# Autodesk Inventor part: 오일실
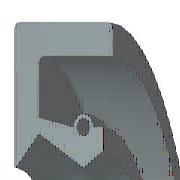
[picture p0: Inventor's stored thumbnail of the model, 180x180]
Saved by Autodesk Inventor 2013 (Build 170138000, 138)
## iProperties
Created: 2021-07
Part Number: 오일실
Material: 고무
Description: 오일-실
Document SubType Name: Modeling
Standard: KS B 2804
Designer: mdu
Standards Organization: KS
Language: ko-KR
Size Designation: D - 10 20 7
Categories: <MemberInstance><Categories><Category DisplayName="샤프트 부품" InternalName="7f7aeb1f-a693-4053-b835-cee3144e0d98" Mnemonic="SHFT"><Category DisplayName="실링" Intern
Density: 0.93 g/cm^3
Mass: 1.11329 g
Surface Area: 16.3871 cm^2
Volume: 1.19708 cm^3
IsCustomPart: 0
Author: mdu
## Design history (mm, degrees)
revolve "본체" stored, may be unused: angle "d17" = 90 deg
revolve "스프링1" stored, may be unused: angle "d18" = 90 deg
body "Solid1"
sketch "스케치1"
  geometry: L1 (0, 10)-(7, 10); L2 (7, 8.25)-(1.75, 8.25); L3 (1.75, 6.75)-(4.9, 5); L4 (4.9, 5)-(0, 5); L5 (0, 0)-(9.586, 0) reference; L6 (4.9, 5)-(6.3, 5.875); L7 (0, 18)-(0, -3) reference; L8 (-1.941, 0)-(11.507, 0) reference; L9 (4.2, 7.1)-(1.75, 7.59); L10 (1.75, 7.59)-(1.75, 8.25); L11 (0, 10)-(0, 5.088); L12 (4.9, 5)-(0, 5); L13 (1.75, 6.75)-(0.152, 5.028); L14 (7, 10)-(7, 8.25); L15 (5.6, 7.1)-(6.3, 7.1); L16 (6.3, 7.1)-(6.3, 5.875); C1 r 0.455 at (4.9, 7.1); A1 r 0.7 centre (4.9, 7.1) between (5.6, 7.1) and (4.2, 7.1); A2 r 0.088 centre (0.088, 5.088) between (0, 5.088) and (0.152, 5.028); 1 further point
  constraints: 28 end point, 5 horizontal alignment, 5 point on line, 4 point on circle, 4 vertical alignment, 3 centre point, 3 tangent, 2 collinear, 2 horizontal, 2 perpendicular, 1 coincident, 1 parallel
  dimensions: "d0" = 20 diameter of L1 L5 (= SD2); "d1" = 1.75 distance of L1.end L2.start (= SD); "d2" = 0.91 diameter of C1 (= SPDI); "d3" = 1.4 diameter of A1 (= SPDA); "d4" = 10 diameter of L3.end L5 (= NND); "d5" = 13.5 diameter of L3.start L5 (= TKDM); "d7" = 15.18 diameter of L9.end L5 (= TKDM + 0.24 x SWDT); "d8" = 1.75 distance between parallel lines of L11 L10 (= SD); "d9" = 4.9 distance from line of L11 C1.centre (= SPDST); "d10" = 14.2 diameter of C1.centre L5 (= HLDM); "d11" = 0.0875 radius of A2 (= 0.25 x LAB); "d12" = 6.3 distance between parallel lines of L11 L16 (= SDI); "d13" = 11.75 diameter of L6.end L5 (= ABDM); "d14" = 7 distance from line of L11 L1.end (= SWDT)
fillet "모깎기1" dims "d6" = 0.3 (= RR)
other parameters: "SD2" = 20 [user parameter; used in 1 equation term], "SWDT" = 7 [user parameter; used in 2 equation terms], "RR" = 0.3 [user parameter; used in 1 equation term], "SD" = 1.75 [user parameter; used in 2 equation terms], "NND" = 10 [user parameter; used in 1 equation term], "SPDA" = 1.4 [user parameter; used in 1 equation term], "SPDI" = 0.91 [user parameter; used in 1 equation term], "TKDM" = 13.5 [user parameter; used in 2 equation terms], "HLDM" = 14.2 [user parameter; used in 1 equation term], "ABDM" = 11.75 [user parameter; used in 1 equation term], "SDI" = 6.3 [user parameter; used in 1 equation term], "SPDST" = 4.9 [user parameter; used in 1 equation term], "LAB" = 0.35 [user parameter; used in 1 equation term], "d15" = 0, "d16" = 0, "d19" = 0
